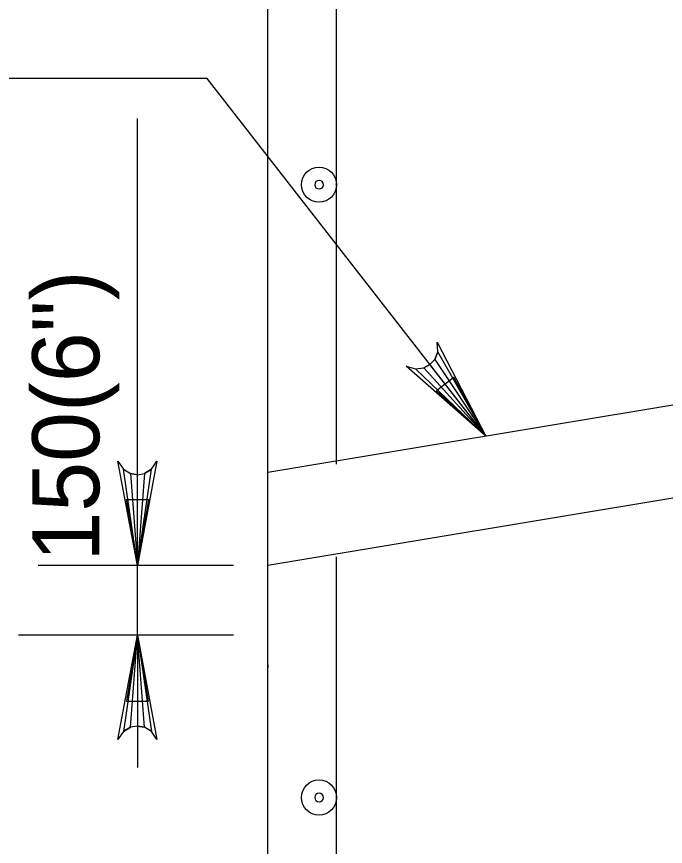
# Model space of a CAD drawing. Extents: x 634540 to 640306, y 296059 to 300275.
# Drawn here: x 639953.47 to 639982.49, y 297648.99 to 297686.1 of the extents above; entities that cross this region are included whole.
import ezdxf

# ---------------------------------------------------------------- set-up
doc = ezdxf.new("R2010")
doc.units = 0
for name, color, linetype in [('3', 7, 'Continuous'), ('4', 7, 'Continuous'), ('6', 7, 'Continuous'), ('9', 7, 'Continuous')]:
    doc.layers.add(name, color=color, linetype=linetype)

# ---------------------------------------------------------------- blocks, each defined once
blk = doc.blocks.new('B')
at = {"layer": '3'}
blk.add_circle((0, 0), 0.1599, dxfattribs=at)
for start, end in [(0, 180), (180, 0)]:
    blk.add_arc((0, 0), 0.0391, start, end, dxfattribs=at)

msp = doc.modelspace()

# ---------------------------------------------------------------- linework, layer by layer
at = {"layer": '3'}
for p, q in [((639962.005, 297683.328), (639951.58, 297683.328)), ((639974.456, 297667.331), (639962.005, 297683.328))]:
    msp.add_line(p, q, dxfattribs=at)
msp.add_lwpolyline([(639973.031, 297669.965), (639972.253, 297669.358), (639974.456, 297667.331)], close=True, dxfattribs=at)
at = {"layer": '4'}
for p, q in [((639958.876, 297667.456), (639958.876, 297681.542)), ((639958.876, 297664.504), (639958.876, 297667.456)), ((639963.176, 297661.552), (639954.446, 297661.552)), ((639958.876, 297658.431), (639958.876, 297661.552)), ((639963.177, 297658.431), (639953.564, 297658.431)), ((639958.155, 297658.431), (639954.446, 297658.431)), ((639958.876, 297655.479), (639958.876, 297652.524))]:
    msp.add_line(p, q, dxfattribs=at)
for points in [[(639974.456, 297667.331), (639970.903, 297670.473), (639971.32, 297670.342), (639971.681, 297670.388), (639971.96, 297670.538), (639972.174, 297670.771), (639972.308, 297671.111), (639972.283, 297671.546), (639974.456, 297667.331), (639972.308, 297671.111), (639972.174, 297670.771), (639974.456, 297667.331), (639971.96, 297670.538), (639971.681, 297670.388), (639974.456, 297667.331), (639971.32, 297670.342)], [(639958.876, 297661.552), (639958.003, 297666.212), (639958.251, 297665.854), (639958.563, 297665.669), (639958.876, 297665.614), (639959.188, 297665.669), (639959.501, 297665.854), (639959.749, 297666.212), (639958.876, 297661.552), (639959.501, 297665.854), (639959.188, 297665.669), (639958.876, 297661.552), (639958.876, 297665.614), (639958.563, 297665.669), (639958.876, 297661.552), (639958.251, 297665.854)], [(639958.876, 297658.431), (639959.749, 297653.77), (639959.501, 297654.129), (639959.188, 297654.314), (639958.876, 297654.368), (639958.563, 297654.314), (639958.251, 297654.129), (639958.003, 297653.77), (639958.876, 297658.431), (639958.251, 297654.129), (639958.563, 297654.314), (639958.876, 297658.431), (639958.876, 297654.368), (639959.188, 297654.314), (639958.876, 297658.431), (639959.501, 297654.129)]]:
    msp.add_lwpolyline(points, dxfattribs=at)
for points in [[(639958.384, 297664.504), (639959.367, 297664.504), (639958.876, 297661.552)], [(639958.384, 297655.479), (639959.367, 297655.479), (639958.876, 297658.431)]]:
    msp.add_lwpolyline(points, close=True, dxfattribs=at)
at = {"layer": '6'}
for p, q in [((639967.778, 297666.089), (639967.778, 297740.253)), ((639967.778, 297644.307), (639967.778, 297661.933))]:
    msp.add_line(p, q, dxfattribs=at)
at = {"layer": '9'}
for p, q in [((639964.714, 297621), (639964.714, 297757.254)), ((639990.504, 297670.006), (639964.714, 297665.708)), ((640007.83, 297668.738), (639964.714, 297661.552)), ((639964.714, 297657.112), (639964.714, 297656.977))]:
    msp.add_line(p, q, dxfattribs=at)

# ---------------------------------------------------------------- block references
at = {"layer": '3', "xscale": 4.921475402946, "yscale": 4.921475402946, "rotation": 90}
for p in [(639967.001, 297678.586), (639967.001, 297651.174)]:
    msp.add_blockref('B', p, dxfattribs=at)

# ---------------------------------------------------------------- texts
at = {"layer": '3'}
msp.add_text('150(6")', height=3.0001, rotation=90, dxfattribs=at).set_placement((639957.172, 297661.725))

doc.saveas('drawing.dxf')
